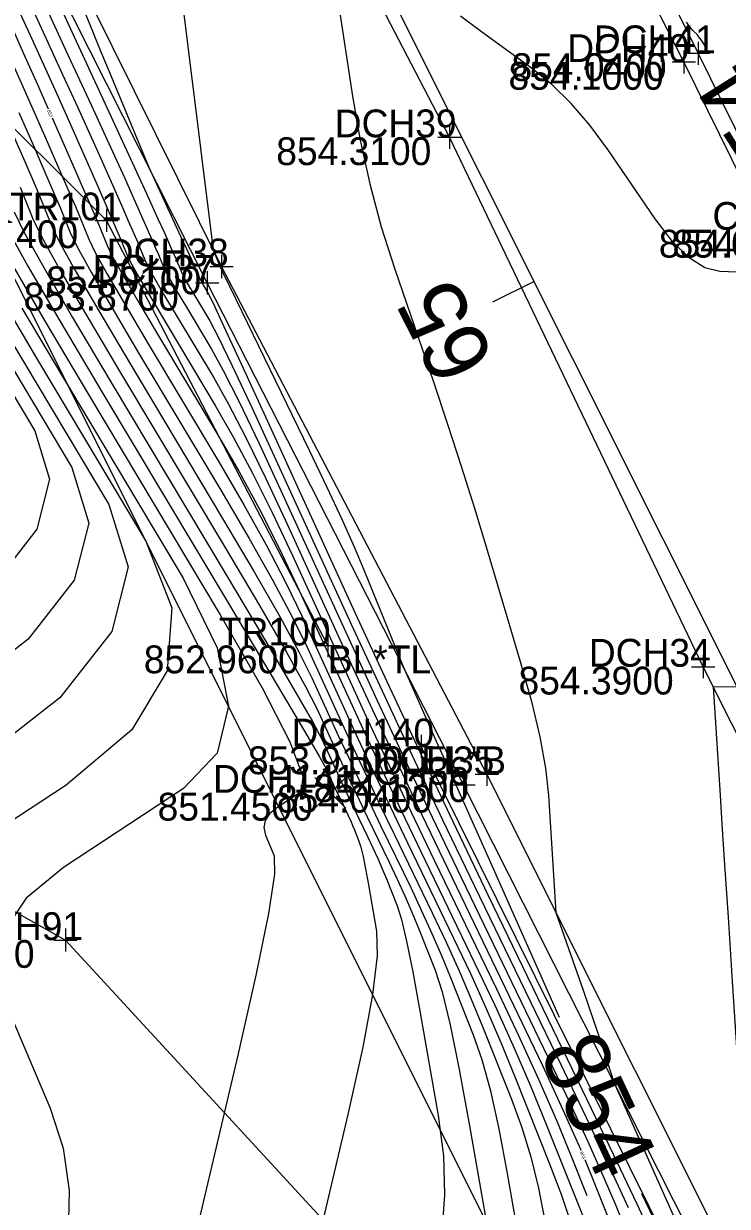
# Model space of a CAD drawing. Extents: x 1654928 to 1810050, y 486881 to 626330.
# Drawn here: x 1801428 to 1801458.4, y 489746.3 to 489797.4 of the extents above; entities that cross this region are included whole.
import ezdxf

# ---------------------------------------------------------------- set-up
doc = ezdxf.new("R2010")
doc.units = 0
for name, color, linetype in [('DT_X_Contour_Major', 7, 'Continuous'), ('DT_X_Contour_Minor', 7, 'Continuous'), ('PV_X_EOP', 7, 'Continuous'), ('PV_X_Shoulder', 7, 'Continuous'), ('RW_X_Esmt_SH', 7, 'Continuous'), ('SV_X_Break_Lines', 7, 'Continuous'), ('SV_X_Center_of_Pavt', 7, 'Continuous'), ('SV_X_CL_Survey_20', 7, 'Continuous'), ('SV_X_Occupation_Line', 7, 'Continuous'), ('SV_X_Random_Point', 7, 'Continuous'), ('SV_X_Shot_Marker', 7, 'Continuous'), ('SV_X_Text_Comment', 7, 'Continuous'), ('SV_X_Text_Elevation', 7, 'Continuous'), ('SV_X_Text_Name', 7, 'Continuous'), ('UT_X_Telecom', 7, 'Continuous')]:
    doc.layers.add(name, color=color, linetype=linetype)

msp = doc.modelspace()

# ---------------------------------------------------------------- linework, layer by layer
at = {"layer": 'DT_X_Contour_Major'}
for points in [[(1801433.989, 489805.29), (1801436.199, 489787.603), (1801436.297, 489787.351), (1801436.323, 489787.288), (1801436.354, 489787.214), (1801436.443, 489787), (1801436.574, 489786.719), (1801436.902, 489786.035), (1801437.427, 489784.949), (1801438.148, 489783.461), (1801440.333, 489778.956), (1801441.095, 489777.366), (1801441.744, 489775.974), (1801442.278, 489774.782), (1801442.698, 489773.788), (1801444.394, 489769.615), (1801445.823, 489766.403), (1801446.206, 489765.543), (1801448.269, 489760.901), (1801451.12, 489754.487)], [(1801427.561, 489798.466), (1801428.296, 489796.87), (1801428.944, 489795.451), (1801429.505, 489794.208), (1801429.979, 489793.142), (1801431.127, 489790.536), (1801431.516, 489789.651), (1801431.821, 489788.951), (1801432.043, 489788.436), (1801432.181, 489788.105), (1801432.437, 489787.471), (1801432.619, 489787.099), (1801432.973, 489786.459), (1801433.499, 489785.552), (1801434.196, 489784.377), (1801436.283, 489780.887), (1801437.078, 489779.501), (1801437.898, 489777.961), (1801438.742, 489776.266), (1801439.611, 489774.418), (1801441.961, 489769.283), (1801442.858, 489767.338), (1801443.786, 489765.353), (1801444.745, 489763.329), (1801445.735, 489761.266), (1801448.417, 489755.712), (1801449.375, 489753.694), (1801450.237, 489751.805), (1801451.004, 489750.045), (1801451.676, 489748.414), (1801452.324, 489746.788)], [(1801457.506, 489796.277), (1801457.273, 489796.634), (1801457.077, 489796.907), (1801456.898, 489797.074), (1801456.822, 489797.156), (1801456.728, 489797.279), (1801456.615, 489797.441)], [(1801427.862, 489790.314), (1801428.414, 489788.95), (1801428.805, 489788.15), (1801429.565, 489786.776), (1801430.694, 489784.826), (1801432.192, 489782.3), (1801436.679, 489774.798), (1801438.191, 489772.252), (1801439.359, 489770.237), (1801440.186, 489768.755), (1801440.67, 489767.806), (1801441.504, 489765.983), (1801441.822, 489765.293), (1801442.151, 489764.589), (1801442.492, 489763.871), (1801442.843, 489763.139), (1801443.794, 489761.168), (1801444.141, 489760.436), (1801444.465, 489759.719), (1801444.769, 489759.015), (1801445.051, 489758.327), (1801445.775, 489756.509), (1801446.071, 489755.578), (1801446.416, 489754.148), (1801446.81, 489752.219), (1801447.253, 489749.791), (1801448.499, 489742.651)], [(1801426.979, 489785.623), (1801428.57, 489782.931), (1801433.297, 489775.029), (1801434.41, 489772.148), (1801434.207, 489769.433), (1801432.686, 489766.884), (1801429.847, 489764.501), (1801420.522, 489758.368)], [(1801454.671, 489746.876), (1801455.208, 489745.764)]]:
    msp.add_lwpolyline(points, dxfattribs=at)
at = {"layer": 'DT_X_Contour_Minor'}
for points in [[(1801426.144, 489805.566), (1801431.518, 489793.935), (1801432.543, 489791.716), (1801433.313, 489790.044), (1801433.828, 489788.92), (1801434.089, 489788.343), (1801434.445, 489787.534), (1801434.566, 489787.26), (1801434.661, 489787.042), (1801434.729, 489786.882), (1801434.772, 489786.78), (1801434.852, 489786.583), (1801434.908, 489786.468), (1801435.018, 489786.269), (1801435.181, 489785.988), (1801435.397, 489785.623), (1801436.045, 489784.54), (1801436.411, 489783.85), (1801437.021, 489782.595), (1801437.876, 489780.773), (1801438.976, 489778.385), (1801442.236, 489771.263), (1801443.48, 489768.564), (1801444.767, 489765.811), (1801446.097, 489763.004), (1801447.471, 489760.142), (1801451.19, 489752.438), (1801452.444, 489749.827), (1801453.416, 489747.769), (1801454.106, 489746.266)], [(1801426.058, 489803.064), (1801428.702, 489797.341), (1801429.612, 489795.368), (1801430.356, 489793.745), (1801430.935, 489792.469), (1801431.349, 489791.543), (1801432.233, 489789.535), (1801432.533, 489788.854), (1801432.768, 489788.315), (1801432.938, 489787.918), (1801433.045, 489787.663), (1801433.242, 489787.175), (1801433.382, 489786.888), (1801433.655, 489786.396), (1801434.059, 489785.697), (1801434.596, 489784.792), (1801436.204, 489782.104), (1801436.856, 489780.951), (1801437.606, 489779.506), (1801438.453, 489777.769), (1801439.4, 489775.74), (1801442.053, 489769.943), (1801443.066, 489767.746), (1801444.113, 489765.506), (1801445.196, 489763.221), (1801446.314, 489760.892), (1801449.341, 489754.621), (1801450.398, 489752.405), (1801451.297, 489750.46), (1801452.038, 489748.786), (1801452.065, 489748.722)], [(1801426.63, 489803.169), (1801429.844, 489796.215), (1801430.927, 489793.867), (1801431.768, 489792.039), (1801432.365, 489790.731), (1801432.719, 489789.943), (1801433.339, 489788.535), (1801433.549, 489788.057), (1801433.714, 489787.679), (1801433.834, 489787.4), (1801433.908, 489787.222), (1801434.047, 489786.879), (1801434.145, 489786.678), (1801434.336, 489786.332), (1801434.62, 489785.842), (1801434.997, 489785.208), (1801436.124, 489783.322), (1801436.633, 489782.401), (1801437.313, 489781.05), (1801438.165, 489779.271), (1801439.188, 489777.063), (1801442.144, 489770.603), (1801443.273, 489768.155), (1801444.44, 489765.659), (1801445.647, 489763.113), (1801446.892, 489760.517), (1801450.266, 489753.53), (1801451.421, 489751.116), (1801452.357, 489749.114), (1801453.072, 489747.526), (1801453.568, 489746.35), (1801454.598, 489743.765)], [(1801440.848, 489803.128), (1801442.202, 489794.233), (1801442.534, 489792.337), (1801442.95, 489790.461), (1801443.449, 489788.605), (1801444.031, 489786.77), (1801445.696, 489781.902), (1801446.309, 489780.08), (1801446.9, 489778.262), (1801447.469, 489776.45), (1801448.016, 489774.642), (1801449.445, 489769.83), (1801449.923, 489768.115), (1801450.284, 489766.581), (1801450.529, 489765.228), (1801450.658, 489764.056), (1801450.986, 489759.007), (1801452.152, 489755.655), (1801452.386, 489754.979), (1801452.589, 489754.387), (1801452.761, 489753.88), (1801452.902, 489753.457), (1801453.485, 489751.681), (1801456.824, 489744.195)], [(1801430.707, 489797.756), (1801431.016, 489796.977), (1801431.348, 489796.158), (1801431.701, 489795.301), (1801433.399, 489791.209), (1801434.792, 489788.193), (1801435.058, 489787.618), (1801435.257, 489787.185), (1801435.391, 489786.893), (1801435.459, 489786.743), (1801435.551, 489786.534), (1801435.582, 489786.463), (1801435.607, 489786.406), (1801435.625, 489786.365), (1801435.636, 489786.338), (1801435.657, 489786.287), (1801435.671, 489786.257), (1801435.7, 489786.206), (1801435.742, 489786.133), (1801435.798, 489786.038), (1801435.966, 489785.757), (1801436.188, 489785.3), (1801436.729, 489784.14), (1801437.587, 489782.276), (1801438.764, 489779.708), (1801442.328, 489771.922), (1801443.687, 489768.973), (1801445.094, 489765.964), (1801446.548, 489762.896), (1801448.049, 489759.768), (1801452.115, 489751.347), (1801453.467, 489748.538), (1801454.476, 489746.424), (1801455.14, 489745.007)], [(1801467.18, 489776.791), (1801467.009, 489777.063), (1801464.656, 489780.803), (1801463.754, 489782.209), (1801463.541, 489782.543), (1801463.288, 489782.942), (1801462.995, 489783.407), (1801462.662, 489783.936), (1801461.017, 489786.56), (1801458.059, 489786.668), (1801457.409, 489786.828), (1801456.726, 489787.262), (1801456.01, 489787.969), (1801455.261, 489788.95), (1801453.219, 489791.931), (1801452.443, 489792.987), (1801451.645, 489793.918), (1801450.825, 489794.725), (1801449.983, 489795.408), (1801447.709, 489797.063), (1801446.866, 489797.696)], [(1801427.532, 489797.157), (1801428.075, 489795.947), (1801428.609, 489794.742), (1801429.074, 489793.687)], [(1801427.239, 489796.342), (1801428.915, 489792.537), (1801429.483, 489791.245), (1801429.928, 489790.223), (1801430.252, 489789.471), (1801430.453, 489788.989), (1801430.828, 489788.062), (1801431.094, 489787.519), (1801431.61, 489786.586), (1801432.377, 489785.261), (1801433.394, 489783.546), (1801436.441, 489778.451), (1801437.523, 489776.601), (1801438.482, 489774.871), (1801439.32, 489773.262), (1801440.035, 489771.773), (1801441.778, 489767.963), (1801442.444, 489766.52), (1801443.132, 489765.047), (1801443.844, 489763.546), (1801444.578, 489762.015), (1801446.568, 489757.894), (1801447.292, 489756.364), (1801447.971, 489754.864), (1801448.606, 489753.394), (1801449.196, 489751.953), (1801450.71, 489748.153), (1801451.225, 489746.802), (1801451.634, 489745.599)], [(1801427.809, 489793.537), (1801428.466, 489792.042), (1801428.982, 489790.859), (1801429.356, 489789.989), (1801429.59, 489789.43), (1801430.023, 489788.358), (1801430.331, 489787.73), (1801430.928, 489786.649), (1801431.816, 489785.116), (1801432.994, 489783.131), (1801436.521, 489777.234), (1801437.746, 489775.151), (1801438.775, 489773.327), (1801439.608, 489771.76), (1801440.246, 489770.451), (1801441.687, 489767.303), (1801442.237, 489766.111), (1801442.805, 489764.895), (1801443.393, 489763.654), (1801444, 489762.39), (1801445.643, 489758.986), (1801446.241, 489757.721), (1801446.802, 489756.482), (1801447.327, 489755.268), (1801447.814, 489754.078), (1801449.065, 489750.938), (1801449.507, 489749.727), (1801449.895, 489748.449), (1801450.228, 489747.103), (1801450.508, 489745.69)], [(1801429.243, 489793.302), (1801430.021, 489791.536), (1801430.499, 489790.448), (1801430.875, 489789.587), (1801431.147, 489788.953), (1801431.317, 489788.547), (1801431.633, 489787.766), (1801431.857, 489787.309), (1801432.292, 489786.522), (1801432.938, 489785.407), (1801433.795, 489783.962), (1801436.362, 489779.669), (1801437.301, 489778.051), (1801438.19, 489776.416), (1801439.031, 489774.764), (1801439.823, 489773.095), (1801441.87, 489768.623), (1801442.651, 489766.929), (1801443.459, 489765.2), (1801444.294, 489763.438), (1801445.157, 489761.641), (1801447.492, 489756.803), (1801448.342, 489755.007), (1801449.139, 489753.246), (1801449.884, 489751.52), (1801450.577, 489749.829), (1801452.355, 489745.367)], [(1801427.529, 489792.658), (1801428.071, 489791.415), (1801428.47, 489790.486), (1801428.726, 489789.872), (1801429.218, 489788.654), (1801429.568, 489787.94), (1801430.247, 489786.712), (1801431.255, 489784.971), (1801432.593, 489782.716), (1801436.6, 489776.016), (1801437.968, 489773.701), (1801439.067, 489771.782), (1801439.897, 489770.257), (1801440.458, 489769.128), (1801441.595, 489766.643), (1801442.029, 489765.702), (1801442.478, 489764.742), (1801442.942, 489763.763), (1801443.421, 489762.764), (1801444.719, 489760.077), (1801445.191, 489759.079), (1801445.634, 489758.1), (1801446.048, 489757.141), (1801446.433, 489756.202), (1801447.42, 489753.724), (1801447.789, 489752.652), (1801448.155, 489751.298), (1801448.519, 489749.661), (1801448.88, 489747.741), (1801449.84, 489742.242)], [(1801427.609, 489789.246), (1801428.042, 489788.361), (1801428.884, 489786.839), (1801430.133, 489784.681), (1801431.792, 489781.885), (1801436.759, 489773.581), (1801438.413, 489770.802), (1801439.652, 489768.692), (1801440.475, 489767.253), (1801440.882, 489766.483), (1801441.615, 489764.884), (1801441.824, 489764.436), (1801442.041, 489763.979), (1801442.264, 489763.513), (1801442.87, 489762.259), (1801443.09, 489761.793), (1801443.297, 489761.337), (1801443.49, 489760.889), (1801443.67, 489760.451), (1801444.131, 489759.294), (1801444.32, 489758.695), (1801444.543, 489757.766), (1801444.799, 489756.506), (1801445.089, 489754.916), (1801445.906, 489750.235), (1801446.128, 489748.504), (1801446.182, 489746.822), (1801446.068, 489745.188)], [(1801427.279, 489788.571), (1801428.202, 489786.902), (1801429.573, 489784.535), (1801431.391, 489781.47), (1801436.838, 489772.363), (1801438.636, 489769.352), (1801439.944, 489767.148), (1801440.763, 489765.751), (1801441.093, 489765.161), (1801441.321, 489764.664), (1801441.408, 489764.475), (1801441.59, 489764.088), (1801441.686, 489763.888), (1801441.945, 489763.35), (1801442.04, 489763.151), (1801442.128, 489762.955), (1801442.211, 489762.763), (1801442.288, 489762.575), (1801442.486, 489762.08), (1801442.567, 489761.823), (1801442.662, 489761.425), (1801442.772, 489760.885), (1801442.896, 489760.203), (1801443.247, 489758.197), (1801443.267, 489757.139), (1801443.067, 489755.467), (1801442.646, 489753.183), (1801442.003, 489750.285), (1801439.995, 489741.742)], [(1801427.475, 489787.041), (1801428.911, 489784.559), (1801430.811, 489781.355), (1801436.497, 489771.848), (1801438.314, 489768.696), (1801439.502, 489766.372), (1801440.058, 489764.875), (1801439.985, 489764.206), (1801438.949, 489763.524), (1801438.626, 489763.259), (1801438.437, 489762.973), (1801438.38, 489762.668), (1801438.455, 489762.342), (1801438.833, 489761.448), (1801438.841, 489760.659), (1801438.58, 489758.963), (1801438.051, 489756.359), (1801437.253, 489752.849), (1801434.768, 489742.279)], [(1801425.208, 489785.296), (1801428.496, 489779.8), (1801429.135, 489777.708), (1801428.59, 489775.554), (1801426.858, 489773.339)], [(1801427.945, 489785.091), (1801429.69, 489782.143), (1801434.897, 489773.438), (1801436.362, 489770.422), (1801436.854, 489767.902), (1801436.372, 489765.88), (1801434.916, 489764.353), (1801429.735, 489760.946), (1801428.124, 489759.618), (1801427.175, 489758.191)], [(1801426.329, 489784.508), (1801430.096, 489778.21), (1801430.829, 489775.812), (1801430.204, 489773.344), (1801428.22, 489770.805), (1801424.877, 489768.195)], [(1801427.449, 489783.72), (1801431.696, 489776.619), (1801432.523, 489773.916), (1801431.818, 489771.134), (1801429.581, 489768.271), (1801425.812, 489765.329)], [(1801466.368, 489768.584), (1801466.023, 489768.621), (1801464.667, 489768.672), (1801457.769, 489768.75), (1801458.069, 489764.069), (1801458.149, 489762.815), (1801458.263, 489761.058), (1801458.409, 489758.798), (1801458.589, 489756.035), (1801459.504, 489741.97)], [(1801427.267, 489755.036), (1801429.157, 489750.563), (1801429.716, 489748.836), (1801429.976, 489747.009), (1801429.937, 489745.082), (1801429.598, 489743.056), (1801428.297, 489737.519), (1801427.897, 489735.62)], [(1801452.226, 489748.334), (1801452.622, 489747.382), (1801453.969, 489744.002)]]:
    msp.add_lwpolyline(points, dxfattribs=at)
at = {"layer": 'PV_X_EOP'}
for points in [[(1801533.684, 489642.188), (1801522.484, 489664.508), (1801511.881, 489685.341), (1801500.299, 489708.684), (1801491.104, 489726.659), (1801480.832, 489747.383), (1801466.882, 489774.659), (1801456.506, 489795.715), (1801444.637, 489819.009), (1801433.258, 489841.444), (1801422.029, 489863.995), (1801410.905, 489885.928), (1801399.817, 489908.089), (1801388.576, 489930.656), (1801376.228, 489955.188), (1801366.008, 489975.62), (1801354.725, 489997.894)], [(1801513.785, 489634.043), (1801503.26, 489654.965), (1801492.692, 489675.84), (1801481.803, 489697.704), (1801472.078, 489717.629), (1801460.782, 489739.414), (1801448.005, 489764.97), (1801436.553, 489786.89), (1801425.237, 489809.697), (1801414.345, 489830.894), (1801402.21, 489854.742), (1801391.781, 489876.056), (1801380.008, 489899.32), (1801369.395, 489920.807), (1801356.62, 489946.308), (1801346.845, 489965.404), (1801335.257, 489988.444)]]:
    msp.add_lwpolyline(points, dxfattribs=at)
at = {"layer": 'PV_X_Shoulder'}
for points in [[(1801534.471, 489642.456), (1801522.963, 489664.954), (1801512.6, 489685.485), (1801500.973, 489709.112), (1801491.766, 489727.019), (1801481.526, 489747.768), (1801467.484, 489775.07), (1801457.116, 489796.092), (1801445.57, 489819.398), (1801434.029, 489841.927), (1801422.682, 489864.343), (1801411.885, 489886.25), (1801400.664, 489908.455), (1801366.703, 489976.232), (1801355.676, 489998.276)], [(1801513.053, 489633.484), (1801502.425, 489654.401), (1801492.155, 489675.438), (1801481.048, 489697.245), (1801471.095, 489717.056), (1801459.974, 489738.844), (1801446.996, 489764.517), (1801435.938, 489786.184), (1801424.33, 489809.156), (1801413.386, 489830.353), (1801401.606, 489854.259), (1801390.811, 489875.349), (1801379.301, 489898.985), (1801368.607, 489920.204), (1801355.561, 489945.921), (1801346.174, 489964.922), (1801334.144, 489988.199)]]:
    msp.add_lwpolyline(points, dxfattribs=at)
at = {"layer": 'RW_X_Esmt_SH'}
msp.add_line((1801533.563, 489574.54), (1801308.538, 490024.454), dxfattribs=at)
at = {"layer": 'SV_X_Break_Lines'}
msp.add_lwpolyline([(1801514.716, 489627.856), (1801503.68, 489648.978), (1801493.699, 489668.787), (1801479.018, 489698.047), (1801467.542, 489721.318), (1801456.644, 489742.996), (1801445.175, 489766.173)], dxfattribs=at)
at = {"layer": 'SV_X_Center_of_Pavt'}
msp.add_lwpolyline([(1801523.585, 489638.313), (1801512.853, 489659.481), (1801502.374, 489680.412), (1801490.819, 489703.952), (1801481.428, 489721.68), (1801470.803, 489742.834), (1801457.335, 489769.613), (1801446.389, 489792.464), (1801435.307, 489813.792), (1801423.54, 489836.522), (1801412.234, 489859.298), (1801401.202, 489881.345), (1801390.005, 489903.67), (1801378.784, 489926.715), (1801366.669, 489950.371), (1801356.567, 489970.63), (1801345.517, 489992.708)], dxfattribs=at)
at = {"layer": 'SV_X_CL_Survey_20'}
for p, q in [((1802886.975, 486913.246), (1801128.538, 490429.055)), ((1802886.975, 486913.246), (1801128.538, 490429.055)), ((1801450.043, 489786.24), (1801448.254, 489785.346))]:
    msp.add_line(p, q, dxfattribs=at)
at = {"layer": 'SV_X_Occupation_Line'}
msp.add_lwpolyline([(1801317.131, 489768.671), (1801358.983, 489768.588), (1801397.909, 489769.246), (1801416.492, 489765.323), (1801429.827, 489757.814), (1801441.541, 489745.071), (1801453.578, 489722.317), (1801464.849, 489700.041), (1801476.834, 489674.228), (1801497.657, 489627.098)], dxfattribs=at)
at = {"layer": 'SV_X_Random_Point'}
for p, q in [((1801440.585, 489763.501), (1801441.919, 489764.836)), ((1801440.585, 489764.836), (1801441.919, 489763.501))]:
    msp.add_line(p, q, dxfattribs=at)
at = {"layer": 'SV_X_Shot_Marker'}
for p, q in [((1801456.506, 489796.215), (1801456.506, 489795.215)), ((1801457.116, 489796.592), (1801457.116, 489795.592)), ((1801456.006, 489795.715), (1801457.006, 489795.715)), ((1801456.506, 489795.715), (1801456.506, 489795.715)), ((1801456.616, 489796.092), (1801457.616, 489796.092)), ((1801457.116, 489796.092), (1801457.116, 489796.092)), ((1801446.389, 489792.964), (1801446.389, 489791.964)), ((1801445.889, 489792.464), (1801446.889, 489792.464)), ((1801446.389, 489792.464), (1801446.389, 489792.464)), ((1801431.587, 489789.379), (1801431.587, 489788.379)), ((1801431.087, 489788.879), (1801432.087, 489788.879)), ((1801431.587, 489788.879), (1801431.587, 489788.879)), ((1801436.553, 489787.39), (1801436.553, 489786.39)), ((1801435.938, 489786.684), (1801435.938, 489785.684)), ((1801436.053, 489786.89), (1801437.053, 489786.89)), ((1801436.553, 489786.89), (1801436.553, 489786.89)), ((1801435.438, 489786.184), (1801436.438, 489786.184)), ((1801435.938, 489786.184), (1801435.938, 489786.184)), ((1801441.137, 489771.028), (1801441.137, 489770.028)), ((1801440.637, 489770.528), (1801441.637, 489770.528)), ((1801441.137, 489770.528), (1801441.137, 489770.528)), ((1801457.335, 489770.113), (1801457.335, 489769.113)), ((1801456.835, 489769.613), (1801457.835, 489769.613)), ((1801457.335, 489769.613), (1801457.335, 489769.613)), ((1801445.175, 489766.673), (1801445.175, 489765.673)), ((1801444.675, 489766.173), (1801445.675, 489766.173)), ((1801445.175, 489766.173), (1801445.175, 489766.173)), ((1801448.005, 489765.47), (1801448.005, 489764.47)), ((1801446.996, 489765.017), (1801446.996, 489764.017)), ((1801447.505, 489764.97), (1801448.505, 489764.97)), ((1801448.005, 489764.97), (1801448.005, 489764.97)), ((1801446.496, 489764.517), (1801447.496, 489764.517)), ((1801446.996, 489764.517), (1801446.996, 489764.517)), ((1801429.827, 489758.314), (1801429.827, 489757.314)), ((1801429.327, 489757.814), (1801430.327, 489757.814)), ((1801429.827, 489757.814), (1801429.827, 489757.814))]:
    msp.add_line(p, q, dxfattribs=at)
at = {"layer": 'UT_X_Telecom'}
msp.add_lwpolyline([(1801441.137, 489770.528), (1801431.587, 489788.879), (1801425.735, 489794.702), (1801417.855, 489797.975), (1801411.771, 489811.027), (1801414.185, 489815.828), (1801412.772, 489822.984)], dxfattribs=at)

# ---------------------------------------------------------------- texts
at = {"layer": 'DT_X_Contour_Major'}
for rotation, p in [(122.271, (1801462.636, 489790.794)), (295.0137, (1801450.234, 489752.943))]:
    msp.add_text('854', height=2.8, rotation=rotation, dxfattribs=at).set_placement(p)
at = {"layer": 'DT_X_Contour_Minor'}
for rotation, p in [(293.773, (1801429.031, 489793.612)), (292.5908, (1801452.02, 489748.648))]:
    msp.add_text('853', height=0.14, rotation=rotation, dxfattribs=at).set_placement(p)
at = {"layer": 'SV_X_CL_Survey_20'}
msp.add_text('65', height=2.8, rotation=116.572, dxfattribs=at).set_placement((1801448.39, 489782.838))
at = {"layer": 'SV_X_Text_Comment'}
for s, p in [('BL*TL', (1801441.137, 489769.328)), ('EL*B', (1801445.175, 489764.973))]:
    msp.add_text(s, height=1.2, dxfattribs=at).set_placement(p)
at = {"layer": 'SV_X_Text_Elevation'}
for s, p in [('854.1000', (1801448.938, 489794.515)), ('854.0400', (1801449.066, 489794.892)), ('854.3100', (1801438.916, 489791.264)), ('852.8400', (1801423.679, 489787.679)), ('854.0900', (1801455.423, 489787.27)), ('854.1400', (1801456.019, 489787.27)), ('854.0100', (1801428.986, 489785.69)), ('853.8700', (1801428.021, 489784.984)), ('852.9600', (1801433.201, 489769.328)), ('854.3900', (1801449.37, 489768.413)), ('853.9100', (1801437.693, 489764.973)), ('854.0400', (1801438.946, 489763.317)), ('854.1300', (1801440.532, 489763.77)), ('851.4500', (1801433.798, 489762.969)), ('850.7600', (1801421.796, 489756.614))]:
    msp.add_text(s, height=1.2, dxfattribs=at).set_placement(p)
at = {"layer": 'SV_X_Text_Name'}
for s, p in [('DCH41', (1801452.618, 489796.092)), ('DCH40', (1801451.47, 489795.715)), ('DCH39', (1801441.439, 489792.464)), ('TR101', (1801427.43, 489788.879)), ('CNPT10', (1801457.738, 489788.47)), ('DCH38', (1801431.602, 489786.89)), ('DCH37', (1801430.997, 489786.184)), ('TR100', (1801436.442, 489770.528)), ('DCH34', (1801452.403, 489769.613)), ('DCH140', (1801439.573, 489766.173)), ('DCH35', (1801443.064, 489764.97)), ('DCH36', (1801441.979, 489764.517)), ('DCH141', (1801436.188, 489764.169)), ('DCH91', (1801425.32, 489757.814))]:
    msp.add_text(s, height=1.2, dxfattribs=at).set_placement(p)

doc.saveas('drawing.dxf')
